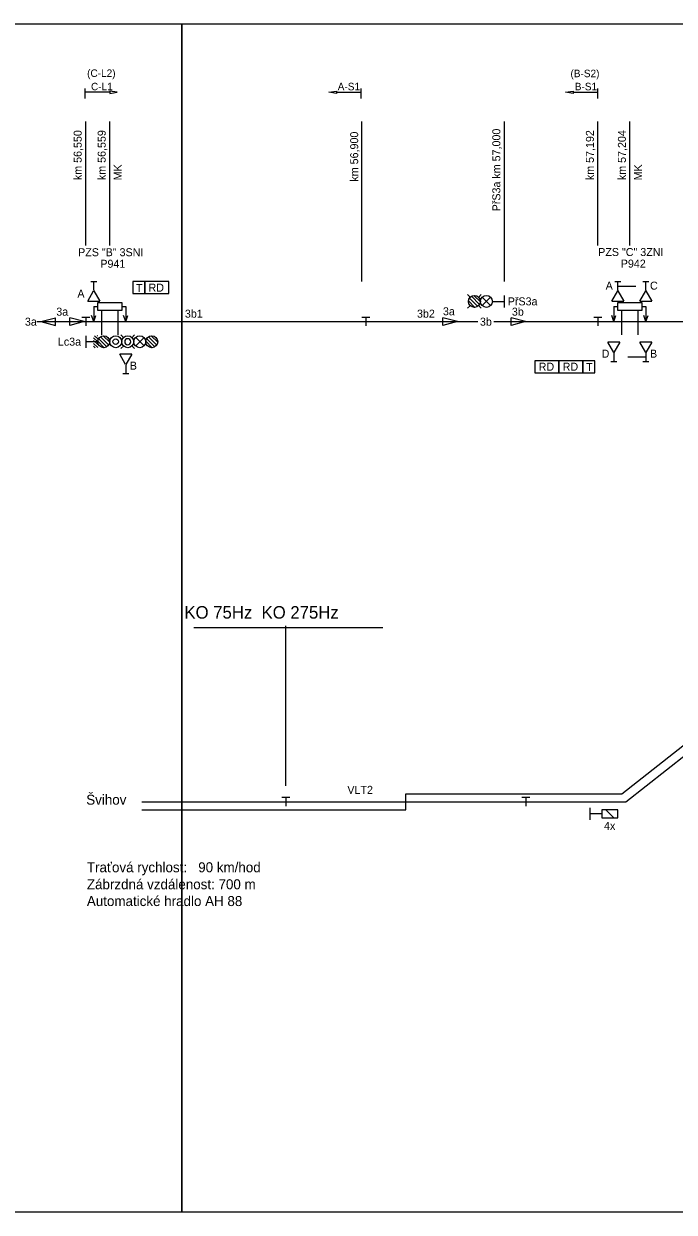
# Model space of a CAD drawing. Extents: x -1146 to 534, y 4 to 301.
# Drawn here: x -765.5 to -602.9, y 4.4 to 301.4 of the extents above; entities that cross this region are included whole.
import ezdxf

# ---------------------------------------------------------------- set-up
doc = ezdxf.new("R2010")
doc.units = 0
for name, color, linetype in [('1', 7, 'Continuous'), ('formát tisku', 7, 'Continuous'), ('kabel', 7, 'Continuous'), ('koleje', 7, 'Continuous'), ('návěstidla', 7, 'Continuous'), ('ostatní', 7, 'Continuous'), ('POPIS', 7, 'Continuous'), ('popisy', 7, 'Continuous'), ('čd', 7, 'Continuous')]:
    doc.layers.add(name, color=color, linetype=linetype)

# ---------------------------------------------------------------- blocks, each defined once
blk = doc.blocks.new('P2')
for p, q in [((2, 6.5), (-2, 6.5)), ((-0.02, 3.02), (-2, 6.5)), ((2, 6.5), (0.02, 3.02)), ((1, 0), (-1, 0)), ((0, 3), (0, 0))]:
    blk.add_line(p, q)
blk = doc.blocks.new('NS14')
for p, q in [((0.1, 18), (-1.5, 16.4)), ((0.8, 17.7), (-1.2, 15.7)), ((1.3, 17.25), (-0.8, 15.2)), ((1.5, 16.6), (-0.1, 15)), ((-1, 11.5), (-1.7, 12.2)), ((1, 11.5), (1.7, 12.2)), ((-1, 9.5), (-1.7, 8.8)), ((1, 9.5), (1.7, 8.8)), ((0.1, 6), (-1.5, 4.4)), ((0.8, 5.7), (-1.2, 3.7)), ((1.3, 5.25), (-0.8, 3.2)), ((1.5, 4.6), (-0.1, 3)), ((0, 3), (0, 0)), ((-1.5, 0), (1.5, 0))]:
    blk.add_line(p, q)
for centre, radius in [((0, 16.5), 1.5), ((0, 13.5), 1.5), ((0, 7.5), 1.5), ((0, 4.5), 1.5), ((0, 7.5), 0.7)]:
    blk.add_circle(centre, radius)
for start, end in [(0, 180), (180, 0)]:
    blk.add_arc((0, 10.5), 0.75, start, end)
blk = doc.blocks.new('NS16')
for p, q in [((-1.499, 0.6437), (-1.1298, 1.0129)), ((-1.4356, 0), (-0.4227, 1.0129)), ((-0.7285, 0), (0.2844, 1.0129)), ((-0.0214, 0), (0.9915, 1.0129)), ((0.6857, 0), (1.499, 0.8133)), ((1.3928, 0), (1.499, 0.1062))]:
    blk.add_line(p, q)
blk = doc.blocks.new('Z22')
for p, q in [((0, 5), (-0.69, 2.9)), ((0, 0), (0, 5)), ((0, 5), (0.69, 2.9))]:
    blk.add_line(p, q)
blk = doc.blocks.new('SB1')
for p, q in [((0, 1.08), (-1, 1.08)), ((1, 1.08), (0, 1.08)), ((0, 1.08), (0, -1.08))]:
    blk.add_line(p, q)
blk = doc.blocks.new('P8')
for p, q in [((2, 6.5), (-2, 6.5)), ((-0.02, 3.02), (-2, 6.5)), ((2, 6.5), (0.02, 3.02)), ((0, 1.5), (-6, 1.5)), ((1, 0), (-1, 0)), ((0, 3), (0, 0))]:
    blk.add_line(p, q)
blk = doc.blocks.new('NS6')
for p, q in [((-1, 8.5), (-1.7, 9.2)), ((0.1, 9), (-1.5, 7.4)), ((1, 8.5), (1.7, 9.2)), ((-1, 6.5), (-1.7, 5.8)), ((0.8, 8.7), (-1.2, 6.7)), ((1.3, 8.25), (-0.8, 6.2)), ((1.5, 7.6), (-0.1, 6)), ((1, 6.5), (1.7, 5.8)), ((0, 3), (0, 0)), ((-1.5, 0), (1.5, 0))]:
    blk.add_line(p, q)
for centre in [(0, 7.5), (0, 4.5)]:
    blk.add_circle(centre, 1.5)
blk = doc.blocks.new('U3')
at = {"layer": '1'}
for p, q in [((1.0002, 4), (-1.0002, 4)), ((-1.0002, 4), (-1.0002, 0)), ((-1.0002, 1.0002), (1.0002, 3.0002)), ((1.0002, 0), (1.0002, 4)), ((-1.0002, 0), (1.0002, 0))]:
    blk.add_line(p, q, dxfattribs=at)
blk = doc.blocks.new('O9')
for p, q in [((-1.5, 3), (-1.5, 0)), ((1.5, 3), (-1.5, 3)), ((1.5, 0), (1.5, 3)), ((-1.5, 0), (1.5, 0))]:
    blk.add_line(p, q)
blk.add_text('T', height=2).set_placement((-0.68, 0.41))
blk = doc.blocks.new('O10')
for p, q in [((3, 3), (-3, 3)), ((-3, 3), (-3, 0)), ((3, 0), (3, 3)), ((-3, 0), (3, 0))]:
    blk.add_line(p, q)
blk.add_text('RD', height=2).set_placement((-2.05, 0.5))

msp = doc.modelspace()

# ---------------------------------------------------------------- linework, layer by layer
for p, q in [((-725.96, 301.44), (-725.96, 292.56)), ((-645.38, 237), (-645.38, 277)), ((-761.17, 227), (-757.54, 227.95)), ((-761.17, 227), (-757.54, 226.05)), ((-750.34, 227), (-753.97, 227.95)), ((-750.34, 227), (-753.97, 226.05)), ((-657.09, 227), (-660.72, 227.95)), ((-657.09, 227), (-660.72, 226.05)), ((-640.06, 227), (-643.69, 227.95)), ((-640.06, 227), (-643.69, 226.05)), ((-624, 105.5), (-624, 102.5)), ((-621, 104), (-624, 104)), ((-725.96, 4.44), (-725.96, 13.33))]:
    msp.add_line(p, q)
msp.add_circle((-739.5, 222), 1.5)
at = {"layer": 'formát tisku'}
for points in [[(-935.96, 301.44), (-725.96, 301.44), (-725.96, 4.44), (-935.96, 4.44)], [(-725.96, 301.44), (-515.96, 301.44), (-515.96, 4.44), (-725.96, 4.44)]]:
    msp.add_lwpolyline(points, close=True, dxfattribs=at)
at = {"layer": 'kabel'}
msp.add_lwpolyline([(-736, 105), (-670, 105), (-670, 109), (-616, 109), (-503, 198), (-500, 195), (-488, 204), (-420, 204)], dxfattribs=at)
at = {"layer": 'koleje'}
for p, q in [((-762.18, 227), (-652, 227)), ((-762.18, 227), (-761.32, 227)), ((-762.18, 227), (-761.32, 227)), ((-648, 227), (-570.35, 227)), ((-648, 227), (-455.86, 227))]:
    msp.add_line(p, q, dxfattribs=at)
msp.add_lwpolyline([(-736, 107), (-615, 107), (-488, 207), (-304, 207)], dxfattribs=at)
at = {"layer": 'návěstidla'}
for p, q in [((-650.95, 233.14), (-648.83, 231.02)), ((-650.95, 231.02), (-648.83, 233.14)), ((-737.51, 223.06), (-735.39, 220.94)), ((-737.51, 220.94), (-735.39, 223.06))]:
    msp.add_line(p, q, dxfattribs=at)
at = {"layer": 'ostatní'}
for p, q in [((-746, 223.75), (-746, 229.75)), ((-742, 229.75), (-742, 223.75)), ((-616, 223.75), (-616, 229.75)), ((-612, 229.75), (-612, 223.75))]:
    msp.add_line(p, q, dxfattribs=at)
at = {"layer": 'POPIS'}
for p, q in [((-723.01, 150.54), (-698.75, 150.53)), ((-700.01, 150.54), (-675.75, 150.53))]:
    msp.add_line(p, q, dxfattribs=at)
at = {"layer": 'popisy'}
for p, q in [((-750.15, 282.8), (-750.15, 285.27)), ((-681.16, 282.8), (-681.16, 285.27)), ((-622.02, 282.8), (-622.02, 285.27)), ((-743.99, 284.33), (-750.24, 284.33)), ((-687.33, 284.33), (-681.08, 284.33)), ((-628.18, 284.33), (-621.93, 284.33)), ((-750, 246), (-750, 277)), ((-744, 246), (-744, 277)), ((-681, 237), (-681, 277)), ((-622, 246), (-622, 277)), ((-614, 246), (-614, 277)), ((-700, 111), (-700, 151))]:
    msp.add_line(p, q, dxfattribs=at)
for points in [[(-743.99, 284.64), (-743.99, 284.02), (-742.11, 284.33)], [(-687.33, 284.64), (-687.33, 284.02), (-689.21, 284.33)], [(-628.18, 284.64), (-628.18, 284.02), (-630.06, 284.33)]]:
    msp.add_lwpolyline(points, close=True, dxfattribs=at)
at = {"layer": 'čd'}
for p, q in [((-748, 230.75), (-747, 230.75)), ((-741, 230.75), (-740, 230.75)), ((-618, 230.75), (-617, 230.75)), ((-611, 230.75), (-610, 230.75)), ((-757.54, 226.05), (-757.54, 227.95)), ((-753.97, 226.05), (-753.97, 227.95)), ((-660.72, 226.05), (-660.72, 227.95)), ((-643.69, 226.05), (-643.69, 227.95))]:
    msp.add_line(p, q, dxfattribs=at)
for points in [[(-747, 231.75), (-741, 231.75), (-741, 229.75), (-747, 229.75)], [(-617, 231.75), (-611, 231.75), (-611, 229.75), (-617, 229.75)]]:
    msp.add_lwpolyline(points, close=True, dxfattribs=at)

# ---------------------------------------------------------------- block references
at = {"rotation": 90}
msp.add_blockref('NS6', (-645.38, 232.07), dxfattribs=at)
at = {"layer": 'koleje'}
msp.add_blockref('SB1', (-680, 227), dxfattribs=at)
at = {"layer": 'návěstidla', "xscale": 0.7499999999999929, "yscale": 0.7499999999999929, "rotation": 180}
for name, p in [('P2', (-748, 237)), ('P8', (-617, 237)), ('P2', (-610, 237))]:
    msp.add_blockref(name, p, dxfattribs=at)
at = {"layer": 'návěstidla'}
for name, p, rotation in [('NS14', (-750, 222), -90.00000000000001), ('NS16', (-747, 222), 90)]:
    msp.add_blockref(name, p, dxfattribs=dict(at, rotation=rotation))
at = {"layer": 'návěstidla', "xscale": 0.7499999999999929, "yscale": 0.7499999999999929}
for name, p in [('P2', (-618, 217)), ('P8', (-610, 217)), ('P2', (-740, 214))]:
    msp.add_blockref(name, p, dxfattribs=at)
at = {"layer": 'čd'}
for name, p in [('O9', (-736.75, 234)), ('O10', (-732.25, 234)), ('SB1', (-750, 227)), ('SB1', (-622, 227)), ('O10', (-634.75, 214.25)), ('O10', (-628.75, 214.25)), ('O9', (-624.25, 214.25)), ('SB1', (-700, 107)), ('SB1', (-640, 107))]:
    msp.add_blockref(name, p, dxfattribs=at)
at = {"layer": 'čd', "xscale": 0.7499999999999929, "yscale": 0.7499999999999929, "rotation": 180}
for p in [(-748, 230.75), (-740, 230.75), (-618, 230.75), (-610, 230.75)]:
    msp.add_blockref('Z22', p, dxfattribs=at)
at = {"layer": 'čd', "rotation": -90.00000000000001}
msp.add_blockref('U3', (-621, 104), dxfattribs=at)

# ---------------------------------------------------------------- texts
for s, height, p in [('(C-L2)', 1.875, (-749.64, 288.16)), ('(B-S2)', 1.875, (-628.86, 288.09)), ('C-L1', 1.875, (-748.68, 284.82)), ('A-S1', 1.875, (-687.02, 284.82)), ('B-S1', 1.875, (-627.78, 284.82)), ('PZS "B" 3SNI', 2, (-751.9, 243.35)), ('PZS "C" 3ZNI', 2, (-621.93, 243.4)), ('P941', 2, (-746.34, 240.47)), ('P942', 2, (-616.29, 240.51)), ('PřS3a', 2, (-644.53, 231.07))]:
    msp.add_text(s, height=height).set_placement(p)
for s, p in [('PřS3a km 57,000', (-646.38, 254.57)), ('MK', (-740.97, 262.32)), ('MK', (-610.97, 262.32))]:
    msp.add_text(s, height=2, rotation=90).set_placement(p)
at = {"layer": 'POPIS'}
msp.add_text('KO 75Hz  KO 275Hz', height=3.125, dxfattribs=at).set_placement((-725.33, 152.79))
at = {"layer": 'popisy'}
for s, p in [('km 56,550', (-751, 262.37)), ('km 56,559', (-745, 262.37)), ('km 56,900', (-681.9, 262)), ('km 57,192', (-623, 262.37)), ('km 57,204', (-615, 262.37))]:
    msp.add_text(s, height=2, rotation=90, dxfattribs=at).set_placement(p)
for s, height, p in [('A', 2, (-752.07, 233)), ('A', 2, (-620.07, 235)), ('C', 2, (-608.98, 235)), ('3a', 2, (-757.35, 228.5)), ('3b1', 2, (-725.21, 228)), ('3b2', 2, (-667.21, 228)), ('3a', 2, (-660.73, 228.59)), ('3b', 2, (-643.5, 228.5)), ('3a', 2, (-765.19, 226)), ('3b', 2, (-651.48, 226)), ('Lc3a', 2, (-756.95, 221)), ('D', 2, (-621.07, 218)), ('B', 2, (-608.98, 218)), ('B', 2, (-738.98, 215)), ('VLT2', 2, (-684.61, 109)), ('Švihov ', 2.5, (-749.86, 106.29)), ('4x', 2, (-620.48, 100)), ('Traťová rychlost:   90 km/hod', 2.5, (-749.7, 89.4)), ('Zábrzdná vzdálenost: 700 m', 2.5, (-749.7, 85.15)), ('Automatické hradlo AH 88', 2.5, (-749.7, 80.96))]:
    msp.add_text(s, height=height, dxfattribs=at).set_placement(p)

doc.saveas('drawing.dxf')
